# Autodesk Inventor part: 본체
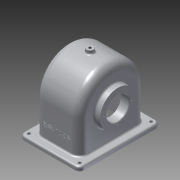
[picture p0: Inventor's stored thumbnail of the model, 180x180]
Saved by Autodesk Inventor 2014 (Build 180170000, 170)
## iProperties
Created: 2016-01
Part Number: 본체
Material: 알루미늄 6061
Document SubType Name: Modeling
Designer: L6
Density: 2.71 g/cm^3
Appearance: 알루미늄 - 평지
Author: L6
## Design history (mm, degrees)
sketch "스케치1"
  geometry: L1 (0, -57)-(-64, -57); L2 (0, 57)-(-64, 57); L3 (-64, -57)-(-64, 57); A1 r 57 centre (0, 0) between (0, -57) and (0, 57); 1 further point
  constraints: 6 end point, 2 point on circle, 2 tangent, 1 centre point, 1 coincident, 1 horizontal, 1 parallel, 1 perpendicular
  dimensions: "d0" = 57 radius of A1; "d1" = 64 distance from line of A1.centre L3
extrude "돌출1" new body sketch "스케치1" distance "d2" = 77; taper "d3" = 0 deg
sketch "스케치2"
  geometry: L1 (0, 0)-(0, 114) reference; L2 (0, 0)-(77, 0) reference; L3 (77, 114)-(77, 0) reference; L4 (0, 114)-(77, 114) reference; L5 (-13.5, 127)-(90.5, 127); L6 (90.5, 127)-(90.5, -13); L7 (90.5, -13)-(-13.5, -13); L8 (-13.5, -13)-(-13.5, 127); 5 further points
  constraints: 8 end point, 4 midpoint, 2 parallel, 1 horizontal, 1 horizontal alignment, 1 perpendicular, 1 vertical alignment
  dimensions: "d5" = 140 distance of L5.end L6.end; "d6" = 104 distance of L5.start L5.end
extrude "돌출2" join sketch "스케치2" distance "d7" = 7; taper "d8" = 0 deg
fillet "모깎기1" dims "d9" = 8
sketch "스케치3"
  geometry: L1 (90.5, -119)-(90.5, 5) reference; C1 r 2.5 at (-5.5, 5); C2 r 2.5 at (-5.5, -119); C3 r 2.5 at (82.5, -119); C4 r 2.5 at (82.5, 5); A1 r 8 centre (-5.5, 5) between (-5.5, 13) and (-13.5, 5) reference; A2 r 8 centre (-5.5, -119) between (-13.5, -119) and (-5.5, -127) reference; A3 r 8 centre (82.5, -119) between (82.5, -127) and (90.5, -119) reference; A4 r 8 centre (82.5, 5) between (90.5, 5) and (82.5, 13) reference; 1 further point
  constraints: 4 centre point, 4 coincident
  dimensions: "d10" = 5 diameter of C4; "d11" = 5 diameter of C1; "d12" = 5 diameter of C2; "d13" = 5 diameter of C3; "d14" = 124 distance of C4.centre C3.centre (derived); "d15" = 8 distance from line of L1 C4.centre (derived)
extrude "돌출3" cut sketch "스케치3" stored distance "d16" = 7; taper "d17" = 0 deg
sketch "스케치4"
  geometry: L1 (90.5, -64)-(-13.5, -64) reference; L2 (-13.5, -64)-(-13.5, -57) reference; L3 (-13.5, -57)-(0, -57) reference; L4 (0, -57)-(0, 57) reference; L5 (0, 57)-(77, 57) reference; L6 (77, 57)-(77, -57) reference; L7 (77, -57)-(90.5, -57) reference; L8 (90.5, -57)-(90.5, -64) reference; L9 (32.5, 57)-(32.5, 63); L10 (32.5, 63)-(44.5, 63); L11 (44.5, 63)-(44.5, 57); L12 (38.5, 63)-(38.5, 46.146); L13 (38.5, 46.146)-(32.5, 46.461); L14 (32.5, 46.461)-(32.5, 63); 1 further point
  constraints: 12 end point, 3 parallel, 1 collinear, 1 midpoint, 1 point on line
  dimensions: "d19" = 12 distance between parallel lines of L9 L11 (derived); "d20" = 6 distance between parallel lines of L5 L10; "d21" = 32.5 distance between parallel lines of L6 L11; "d22" = 32.5 distance between parallel lines of L4 L9
revolve "회전1" sketch "스케치4" stored, may be unused: angle "d23" = 90 deg
fillet "모깎기2" dims "d24" = 3
node "작업 평면1"
sketch "스케치5"
  geometry: L1 (-64, -70)-(-64, 70) reference; L2 (-64, 70)-(-57, 70) reference; L3 (-57, 70)-(-57, 57) reference; L4 (-57, 57)-(0, 57) reference; L5 (0, -57)-(-57, -57) reference; L6 (-57, -57)-(-57, -70) reference; L7 (-57, -70)-(-64, -70) reference; L8 (0, 51)-(-64, 51); L9 (-64, -51)-(0, -51); A1 r 57 centre (0, 0) between (0, -57) and (0, 57) reference; A2 r 51 centre (0, 0) between (0, -51) and (0, 51); 1 further point
  constraints: 4 end point, 2 point on circle, 2 point on line, 1 centre point
  dimensions: "d26" = 6 distance between parallel lines of L5 L9; "d27" = 6 distance between parallel lines of L4 L8; "d29" = 6 radial gap between concentric circles of A1 A2
extrude "돌출4" cut sketch "스케치5" distance "d30" = 67; taper "d31" = 0 deg
sketch "스케치6"
  geometry: L1 (47.5, 57)-(77, 57) reference; L2 (77, 57)-(77, -57) reference; L3 (77, -57)-(90.5, -57) reference; L4 (90.5, -57)-(90.5, -64) reference; L5 (90.5, -64)-(72, -64) reference; L6 (72, -64)-(72, 51) reference; L7 (72, 51)-(5, 51) reference; L8 (5, 51)-(5, -64) reference; L9 (5, -64)-(-13.5, -64) reference; L10 (-13.5, -64)-(-13.5, -57) reference; L11 (-13.5, -57)-(0, -57) reference; L12 (0, -57)-(0, 57) reference; L13 (0, 57)-(29.5, 57) reference; L14 (32.5, 60)-(32.5, 63) reference; L15 (32.5, 63)-(44.5, 63) reference; L16 (44.5, 63)-(44.5, 60) reference; L17 (5, 35.747)-(19, 24); L18 (19, 24)-(19, -4); L19 (19, -4)-(-15.466, -4); L20 (77, 27)-(87, 27); L21 (87, 27)-(87, -4); L22 (87, -35)-(77, -35); L23 (5, 35.747)-(5, -4); L24 (19, -4)-(100.408, -4); L25 (77, 27)-(77, -4); 2 further points
  constraints: 18 end point, 8 point on line, 4 perpendicular, 2 parallel, 1 horizontal alignment, 1 midpoint, 2 other
  dimensions: "d32" = 50 deg angle of L18 L17; "d36" = 60 distance between parallel lines of L9 L19; "d37" = 19 distance between parallel lines of L12 L18; "d38" = 62 distance of L20.end L22.start; "d39" = 87 distance between parallel lines of L12 L21; "d40" = 28 distance of L17.end L18.end; "d41" = 31 distance between parallel lines of L24 L20
revolve "회전2" sketch "스케치6" stored, may be unused: angle "d42" = 90 deg
sketch "스케치7"
  geometry: C1 r 31 at (0, 0) reference; C2 r 20 at (0, 0); 1 further point
  constraints: 1 centre point, 1 coincident
  dimensions: "d43" = 40 diameter of C2
extrude "돌출5" cut sketch "스케치7" stored distance "d44" = 67; taper "d45" = 0 deg
sketch "스케치9"
  geometry: L1 (87, -35)-(77, -35) reference; L2 (77, -35)-(77, -57) reference; L3 (77, -57)-(90.5, -57) reference; L4 (90.5, -57)-(90.5, -64) reference; L5 (90.5, -64)-(72, -64) reference; L6 (72, -64)-(72, -24) reference; L7 (72, -24)-(87, -24) reference; L8 (87, -24)-(87, -35) reference; L9 (19, -32)-(5, -43.747) reference; L10 (5, -43.747)-(5, -64) reference; L11 (5, -64)-(-13.5, -64) reference; L12 (-13.5, -64)-(-13.5, -57) reference; L13 (-13.5, -57)-(0, -57) reference; L14 (0, -57)-(0, -24) reference; L15 (0, -24)-(19, -24) reference; L16 (19, -24)-(19, -32) reference; L17 (47.5, 57)-(77, 57) reference; L18 (77, 57)-(77, 27) reference; L19 (77, 27)-(87, 27) reference; L20 (87, 27)-(87, 16) reference; L21 (87, 16)-(72, 16) reference; L22 (72, 16)-(72, 51) reference; L23 (72, 51)-(5, 51) reference; L24 (5, 51)-(5, 35.747) reference; L25 (5, 35.747)-(19, 24) reference; L26 (19, 24)-(19, 16) reference; L27 (19, 16)-(0, 16) reference; L28 (0, 16)-(0, 57) reference; L29 (0, 57)-(29.5, 57) reference; L30 (32.5, 60)-(32.5, 63) reference; L31 (32.5, 63)-(44.5, 63) reference; L32 (44.5, 63)-(44.5, 60) reference; L33 (0, 33.416)-(3, 30.899); L34 (3, -38.899)-(0, -41.416); L35 (3, 30.899)-(3, -4); L36 (3, -24)-(3, -38.899); L37 (0, 16)-(0, 33.416); L38 (87, -35)-(77, -35) reference; L39 (77, -35)-(77, -57) reference; L40 (77, -57)-(90.5, -57) reference; L41 (90.5, -57)-(90.5, -64) reference; L42 (90.5, -64)-(72, -64) reference; L43 (72, -64)-(72, -24) reference; L44 (72, -24)-(87, -24) reference; L45 (87, -24)-(87, -35) reference; L46 (19, -32)-(5, -43.747) reference; L47 (5, -43.747)-(5, -64) reference; L48 (5, -64)-(-13.5, -64) reference; L49 (-13.5, -64)-(-13.5, -57) reference; L50 (-13.5, -57)-(0, -57) reference; L51 (0, -57)-(0, -24) reference; L52 (0, -24)-(19, -24) reference; L53 (19, -24)-(19, -32) reference; L54 (47.5, 57)-(77, 57) reference; L55 (77, 57)-(77, 27) reference; L56 (77, 27)-(87, 27) reference; L57 (87, 27)-(87, 16) reference; L58 (87, 16)-(72, 16) reference; L59 (72, 16)-(72, 51) reference; L60 (72, 51)-(5, 51) reference; L61 (5, 51)-(5, 35.747) reference; L62 (5, 35.747)-(19, 24) reference; L63 (19, 24)-(19, 16) reference; L64 (19, 16)-(0, 16) reference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; 1 further point
  constraints: 14 end point, 6 parallel, 4 point on line, 1 midpoint, 1 perpendicular, 4 other
  dimensions: "d47" = 5 distance between parallel lines of L9 L34; "d48" = 5 distance between parallel lines of L25 L33; "d50" = 3 distance between parallel lines of L28 L35; "d60" = 60 distance between parallel lines of L11 L72
revolve "회전3" sketch "스케치9" stored, may be unused: angle "d51" = 90 deg
sketch "스케치10"
  geometry: C1 r 6 at (0, 0) reference; 1 further point
hole "구멍1" sketch "스케치10" at (0, 0) diameter "d53" = 4.459; stored, may be unused: countersink angle "d57" = 90 deg, drill point angle "d59" = 118 deg; dims "d54" = 6, "d55" = 4, "d56" = 2, "d58" = 8
sketch "스케치11" dims "d61" = 56
  geometry: L1 (0, 28)-(28, 0); L2 (28, 0)-(0, -28); L3 (0, -28)-(-28, 0); L4 (-28, 0)-(0, 28); C1 r 20 at (0, 0) reference; C2 r 34.899 at (0, 0) reference; A1 r 51 centre (0, 4) between (51, 4) and (-51, 4) reference; 3 further points
  constraints: 8 end point, 2 coincident, 1 vertical alignment, 11 other
  dimensions: "d62" = 40 diameter of C1 (derived); "d64" = 56 distance of L1.start L2.end (derived); "d65" = 56 distance of L1.end L3.end (derived)
hole "구멍2" sketch "스케치11" at (0, 28), (28, 0), (0, -28), (-28, 0) diameter "d67" = 2.459; stored, may be unused: countersink angle "d71" = 90 deg, drill point angle "d73" = 118 deg; dims "d68" = 7, "d69" = 4, "d70" = 2, "d72" = 9
sketch "스케치12" dims "d74" = 48
  geometry: L1 (0, 24)-(24, 0); L2 (24, 0)-(0, -24); L3 (0, -24)-(-24, 0); L4 (-24, 0)-(0, 24); C1 r 31 at (0, 0) reference; 3 further points
  constraints: 8 end point, 2 coincident, 1 vertical alignment, 11 other
hole "구멍3" sketch "스케치12" at (0, 24), (-24, 0), (0, -24), (24, 0) diameter "d75" = 2.459; stored, may be unused: countersink angle "d79" = 90 deg, drill point angle "d81" = 118 deg; dims "d76" = 6, "d77" = 4, "d78" = 2, "d80" = 8
chamfer "모따기1" distance "d82" = 1; stored, may be unused: second distance "d83" = 2, angle "d84" = 45 deg
fillet "모깎기3" dims "d85" = 14, "d86" = 9
fillet "모깎기4" dims "d87" = 3
fillet "모깎기5" dims "d88" = 3
fillet "모깎기6" dims "d89" = 3
sketch "스케치13"
  geometry: L1 (0.004, -28.682)-(48.996, -28.682); L2 (48.996, -28.682)-(48.996, -39.318); L3 (48.996, -39.318)-(0.004, -39.318); L4 (0.004, -39.318)-(0.004, -28.682); L5 (-19.5, -64)-(68.5, -64) reference; L6 (0.004, -28.682)-(48.996, -28.682); L7 (48.996, -28.682)-(48.996, -39.318); L8 (48.996, -39.318)-(0.004, -39.318); L9 (0.004, -39.318)-(0.004, -28.682); L10 (0.004, -34)-(48.996, -34); L11 (24.5, -39.318)-(24.5, -28.682); L12 (-14, 0)-(-14, -54) reference
  constraints: 12 end point, 4 midpoint, 2 parallel, 1 horizontal, 1 perpendicular, 2 other
  dimensions: "d91" = 30 distance from line of L5 L10.start; "d92" = 38.5 distance between parallel lines of L11 L12; "d93" = 10.63678 distance of L1.end L2.end
feature "엠보싱1" sketch "스케치13" dims "d0" = 57, "d1" = 64, "d94" = 0.5, "d95" = 0
node "솔리드1"
node "투영된 루프1"
node "절단 모서리 투영1"
node "절단 모서리 투영2"
node "절단 모서리 투영3"
node "절단 모서리 투영4"
node "절단 모서리 투영5"
other parameters: "d25" = 5, "d49" = 3
